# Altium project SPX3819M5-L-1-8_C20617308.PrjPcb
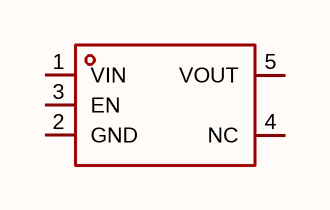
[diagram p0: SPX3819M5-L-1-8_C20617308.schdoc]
1 sheet, 1 parts. Net scope: global (net labels, ports and power ports of the same name join across sheets).

## Sheet SPX3819M5-L-1-8_C20617308.schdoc
size 127 x 101 mm

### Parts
U?  spx3819m5-l-1-8  [SOT-23-5_L2.9-W1.6-P0.95-LS2.8-BR]  (value not drawn)

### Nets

Not connected (* = marked no-connect by the designer): U? 1(VIN) 2(GND) 3(EN) 4(NC) 5(VOUT)

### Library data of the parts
U? = spx3819m5-l-1-8: 输出极性:正极;工作电压:20V;输出电压:1.8V;输出电流:500mA;电源纹波抑制比(PSRR):70dB@(1kHz);输出类型:固定;; Manufacturer: TECH PUBLIC(台舟); Symbol: SPX3819M5-L-1-8_C20617308; AddInBom: yes; ModelId: 7ba65df16e7b4570af156e925f9c37fe; ModelTransform: 114.173,114.173,0,90,0,0,0,0,0; Output Configuration: 正极; Voltage - Supply: 20V; Output Voltage: 1.8V; Output Current: 500mA; Voltage Dropout: 500mV@(100mA); standby current: 5uA; Output Type: 固定; Number of Outputs: 1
